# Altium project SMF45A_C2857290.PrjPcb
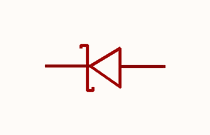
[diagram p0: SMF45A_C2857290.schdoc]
1 sheet, 1 parts. Net scope: global (net labels, ports and power ports of the same name join across sheets).

## Sheet SMF45A_C2857290.schdoc
size 127 x 101 mm

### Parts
D?  smf45a_c2857290  [SOD-123FL_L2.8-W1.8-LS3.6-RD]  (value not drawn)

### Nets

Not connected (* = marked no-connect by the designer): D? 1(K) 2(A)

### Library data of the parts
D? = smf45a_c2857290: 极性:单向;反向截止电压(Vrwm):45V;钳位电压:72.7V;峰值脉冲电流(Ipp):2.8A;峰值脉冲功率(Ppp):200W@10/1000us;击穿电压(VBR):50V;; Manufacturer: JSMSEMI(杰盛微); ManufacturerPart: SMF45A; AddInBom: yes; ModelId: 9a6bf0a398604d2998ad78800a7c8ef9; ModelTransform: 141.732,70.866,0,0,0,0,0,0,0; Polarity: 单向; Reverse Stand-Off Voltage (Vrwm): 45V; Clamping Voltage: 72.7V; Peak Pulse Current (Ipp): 2.8A; Voltage - Breakdown: 50V; Reverse Leakage Current (Ir): 1uA; Number of Channels: 单路; Type: TVS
